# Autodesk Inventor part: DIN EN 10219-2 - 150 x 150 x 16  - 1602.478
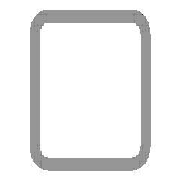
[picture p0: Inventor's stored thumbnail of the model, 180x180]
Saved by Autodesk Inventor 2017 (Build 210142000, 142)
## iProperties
Created: 2017-11
Part Number: DIN EN 10219-2 - 150 x 150 x 16  - 1602.478
Material: Steel, Mild
Description: Cold formed welded structural hollow sections of non-alloy and fine grain structural steel
Document SubType Name: Modeling
Standard: DIN
Designer: iusti
Standard Revision: 2006-07
Standards Organization: DIN
Language: en-US
Size Designation: 150 x 150 x 16
Categories: <MemberInstance><Categories><Category DisplayName="Structural Shapes" InternalName="089c4875-fa83-4c05-b084-43b9cc11f5ed" Mnemonic="GRDR"><CategoryParameter Dis
Stock Number: 150 x 150 x 16
Mass: 88044.5 g
Surface Area: 14205.2 cm^2
Volume: 11215.9 cm^3
Density: 7.85 g/cm^3
Appearance: Semi-Polished
IsCustomPart: 1
G_W: 150.000 mm
G_H: 150.000 mm
G_L: 1602.478 mm
+987C6673-447C-412A-9B24-0CD20188E66E+CUTDETAIL2: Miter 69.88 deg
+D0655DDE-97F9-4B99-A490-E36C02108510+CUTDETAIL3: Miter 45.00 deg
_CCFamilyMember: 76
_CCFamilyDisplayName: DIN EN 10219-2 (Square Hollow Section - Cold Formed) - Cold formed welded structural hollow sections of non-alloy and fine grain structural steel
_FrameMemberDoc: Frame Member File
_Version: 15.0.0
_GetPNFromCC: 1
Author: iusti
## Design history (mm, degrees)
node "Start plane"
node "End plane"
sketch "Sketch"
  geometry: L1 (-75, -27)-(-75, 27); L2 (-27, 75)-(27, 75); L3 (75, 27)-(75, -27); L4 (27, -75)-(-27, -75); L5 (-27, 59)-(27, 59); L6 (59, 27)-(59, -27); L7 (27, -59)-(-27, -59); L8 (-59, -27)-(-59, 27); L9 (0, 118.918)-(0, -118.918) reference; L10 (-118.918, 0)-(118.918, 0) reference; A1 r 48 centre (-27, -27) between (-75, -27) and (-27, -75); A2 r 48 centre (-27, 27) between (-27, 75) and (-75, 27); A3 r 48 centre (27, 27) between (75, 27) and (27, 75); A4 r 48 centre (27, -27) between (27, -75) and (75, -27); A5 r 32 centre (-27, 27) between (-27, 59) and (-59, 27); A6 r 32 centre (27, 27) between (59, 27) and (27, 59); A7 r 32 centre (27, -27) between (27, -59) and (59, -27); A8 r 32 centre (-27, -27) between (-59, -27) and (-27, -59)
  constraints: 16 end point, 16 point on circle, 8 centre point, 8 tangent, 4 parallel, 3 equal radius, 2 perpendicular, 7 other
  dimensions: "d7" = 48 radius of A1 (= G_IR); "d10" = 150 distance between parallel lines of L2 L4 (= G_H); "d11" = 150 distance between parallel lines of L1 L3 (= G_W); "d12" = 16 distance between parallel lines of L3 L6 (= G_T); "d15" = 75 distance between parallel lines of L2 L10 (= 0.5 x d10); "d16" = 75 distance between parallel lines of L9 L3 (= 0.5 x d11)
extrude "Body" new body sketch "Sketch" stored distance "d3" = 1602.4779 (= G_L); taper "d4" = 0 deg
node "Driven Length"
  sketch "Sketch3"
    geometry: L1 (0, 0)-(10, 0) reference
    constraints: 2 end point, 1 horizontal
  workplane "Work Plane3"
  sketch "Sketch4"
    geometry: L1 (-2, -27.478)-(12, -27.478) reference; L2 (-2, 1575)-(12, 1575) reference
    dimensions: "d18" = 1602.4779 distance between parallel lines of L1 L2 (derived)
workplane "Work Plane5"
split "Split2"
workplane "Work Plane6"
split "Split3"
body "Solid1"
other parameters: "G_W" = 150 [user parameter; used in 1 equation term], "G_H" = 150 [user parameter; used in 1 equation term], "G_T" = 16 [user parameter; used in 1 equation term], "G_IR" = 48 [user parameter; used in 1 equation term], "G_L" = 1602.4779 (= d18) [user parameter; used in 1 equation term], "G_OFFSET_START" = 27.4779 [user parameter; used in 1 equation term], "G_OFFSET_END" = 75 [user parameter; used in 1 equation term], "d13" = -27.4779 (= -G_OFFSET_START), "d14" = 1575 (= G_OFFSET_END + B_L), "d17" = 90 deg
